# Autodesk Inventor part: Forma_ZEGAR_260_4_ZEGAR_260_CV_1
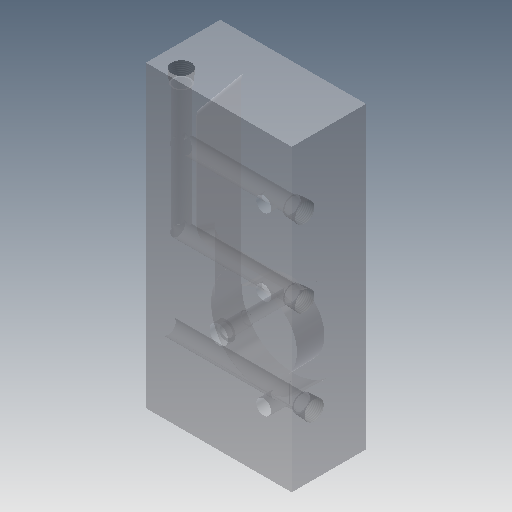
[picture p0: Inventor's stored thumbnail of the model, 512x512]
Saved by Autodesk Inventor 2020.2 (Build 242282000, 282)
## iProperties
Created: 2015-01
Part Number: Forma_ZEGAR_260_4_ZEGAR_260_CV_1
Material: Ogólny
Document SubType Name: Modeling
Designer: F.Stasiak
Density: 1 g/cm^3
Appearance: Domyślna
Catalog Web Link: www.expertbooks.pl
Manager: www.cadconsulting.pl
Company: Fabian Stasiak CAD Consulting
Author: F.Stasiak
Subject: Zbiór ćwiczeń. Autodesk Inventor 2020. Kurs Professional
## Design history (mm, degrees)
node "Forma_ZEGAR_260_4_ZEGAR_260_CV_Base"
feature "Rzeźbienie3"
feature "Rzeźbienie4"
feature "Gwint1" dims "d6" = 0, "d7" = 0
feature "Rzeźbienie15"
feature "Gwint8" dims "d20" = 0, "d21" = 0
feature "Rzeźbienie17"
feature "Gwint10" dims "d24" = 0, "d25" = 0
feature "Rzeźbienie18"
feature "Gwint11" dims "d26" = 0, "d27" = 0
feature "Rzeźbienie19"
feature "Rzeźbienie20"
feature "Rzeźbienie21"
feature "Bryła1::Forma_ZEGAR_260_4_ZEGAR_260_CV_Base"
tag "Bryła wyprowadzona1"
node "Bryła1"
feature "Forma_ZEGAR_260_4_ZEGAR_260_CV_Base_Bodies"
feature "Powierzchnia3"
body "Srf3"
feature "Powierzchnia4"
body "Srf4"
feature "Powierzchnia15"
body "Srf15"
feature "Powierzchnia17"
body "Srf17"
feature "Powierzchnia18"
body "Srf18"
feature "Powierzchnia19"
body "Srf19"
feature "Powierzchnia20"
body "Srf20"
feature "Powierzchnia21"
body "Srf21"
other parameters: "d0" = 0, "d1" = -26.4075, "d3" = 0, "d4" = -180 deg, "d5" = 0
